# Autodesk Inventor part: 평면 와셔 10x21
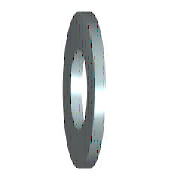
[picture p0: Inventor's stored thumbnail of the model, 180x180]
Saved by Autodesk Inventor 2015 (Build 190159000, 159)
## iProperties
IsCustomPart: 1
Created: 2012-02
Part Number: 평면 와셔 10x21
Material: 강철, 연강
Description: 평면 와셔
Document SubType Name: Modeling
Standard: KS B 1326
Designer: mduedu
Standards Organization: KS
Language: ko-KR
Size Designation: 10x21
Categories: <MemberInstance><Categories><Category DisplayName="조임쇠" InternalName="e4da775c-781d-43d5-af7c-5136215cf5a6" Mnemonic="FSTN"><Category DisplayName="와셔" InternalN
Density: 1 g/cm^3
Appearance: 노란색
Author: mduedu
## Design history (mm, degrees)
sketch "스케치"
  geometry: C1 r 10.5 at (0, 0); C2 r 5.25 at (0, 0); 1 further point
  constraints: 2 centre point, 2 coincident
  dimensions: "d0" = 10.5 diameter of C2 (= SD1); "d1" = 21 diameter of C1 (= SD2)
extrude "본체" new body sketch "스케치" distance "d2" = 2 (= SD); taper "d3" = 0 deg
workaxis "Work Axis1"
workplane "Work Plane1"
body "Solid1"
other parameters: "SD1" = 10.5 [user parameter; used in 1 equation term], "SD2" = 21 [user parameter; used in 1 equation term], "SD" = 2 [user parameter; used in 1 equation term], "d4" = 0, "d5" = 0, "d6" = 0, "d7" = 0
